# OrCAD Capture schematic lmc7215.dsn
size A
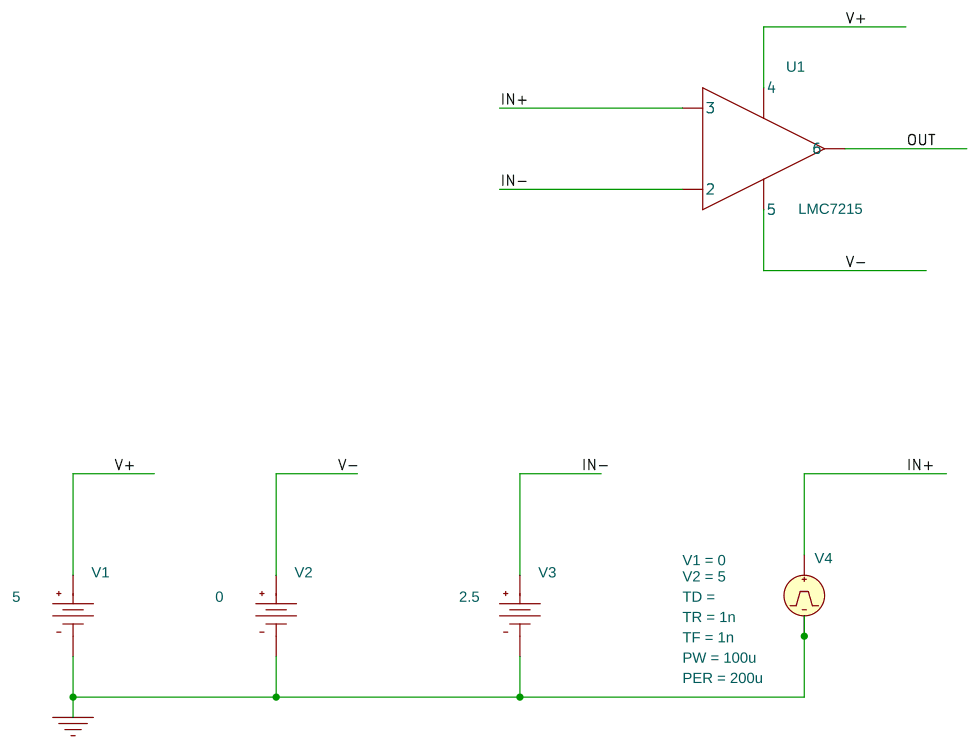
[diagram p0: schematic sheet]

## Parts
U1  LMC7215
V1  VDC
V2  VDC
V3  VDC
V4  VPULSE

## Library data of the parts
U1 = LMC7215
V1 = VDC: DC: 5
V2 = VDC: DC: 0
V3 = VDC: DC: 2.5
V4 = VPULSE: PER: 200u; PW: 100u; TF: 1n; TR: 1n; V1: 0; V2: 5

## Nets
0: V1.1(-) V2.1(-) V3.1(-) V4.2(-)
IN+: U1.IN+(3) V4.1(+)
IN-: U1.IN-(2) V3.0(+)
OUT: U1.OUT(6)
V+: U1.V+(4) V1.0(+)
V-: U1.V-(5) V2.0(+)
